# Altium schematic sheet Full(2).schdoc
size 301 x 189 mm
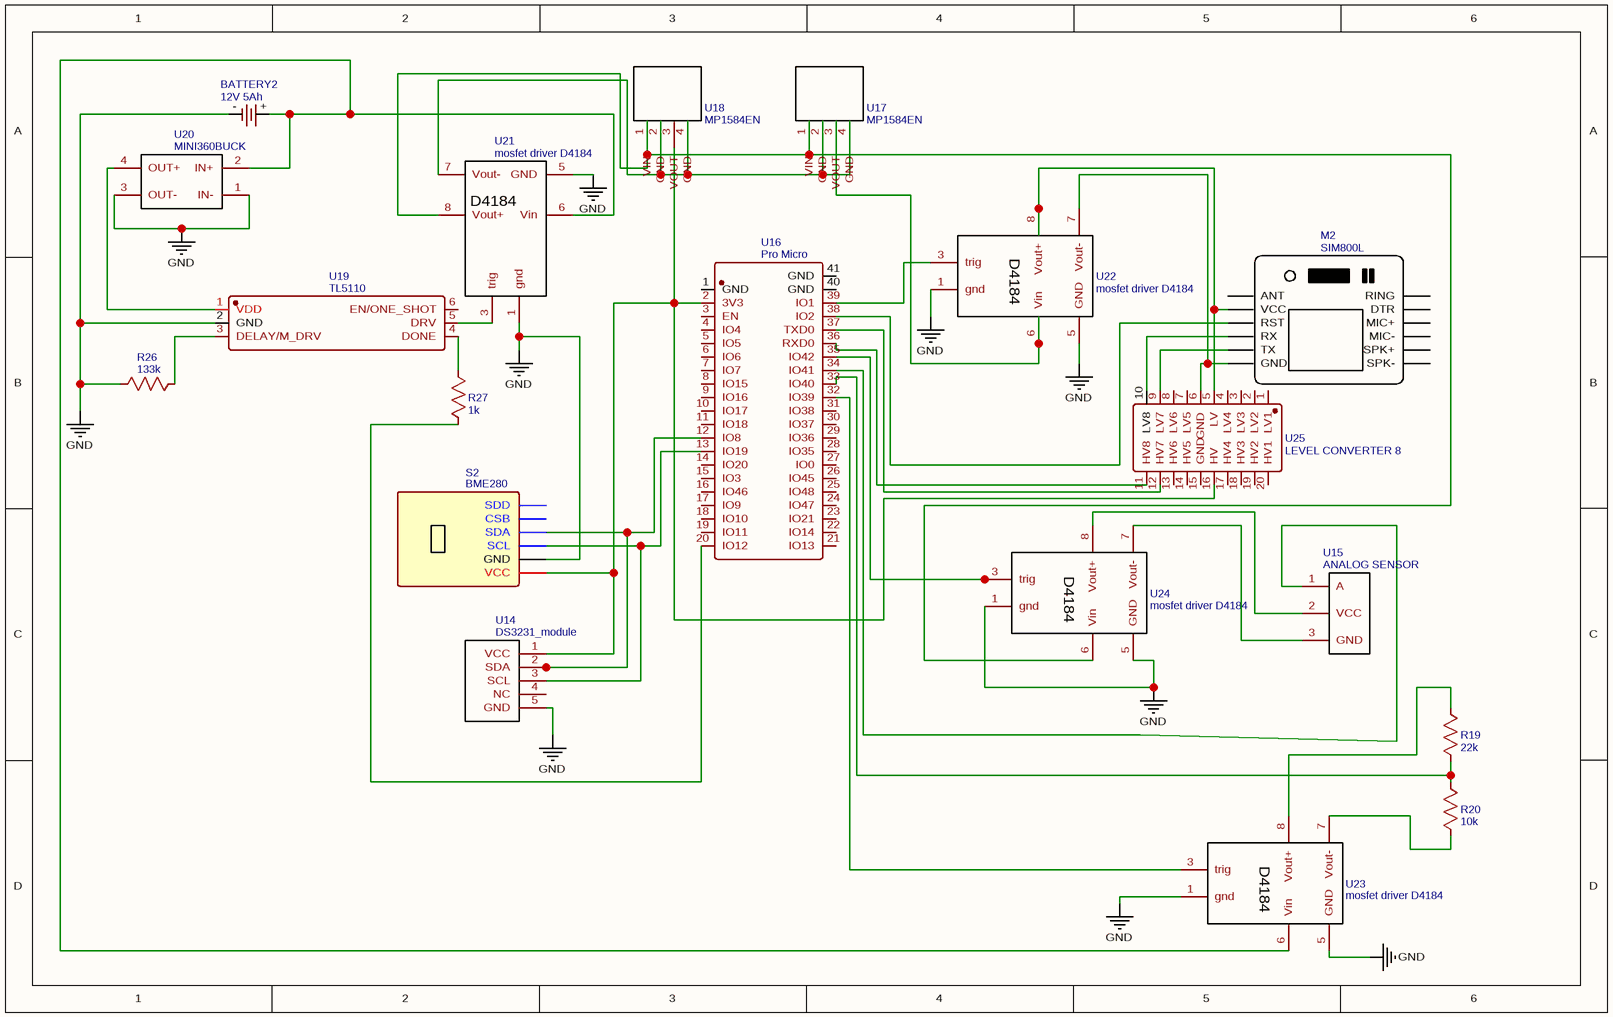
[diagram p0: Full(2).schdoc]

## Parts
BATTERY2  12V 5Ah  [BATTERY-SMD-MY-2032]
M2  SIM800L  [SIM800LMODULE_SIM800LMODULE]
R19  22k  [R0603]
R20  10k  [R0603]
R26  133k  [R0603]
R27  1k  [R0603]
S2  BME280  [BME280]
U14  DS3231_module  [DS3231]
U15  ANALOG SENSOR  [ANALOG SENSOR V1]
U16  Pro Micro  [WIRELM-SMD_ESP32-S3-WROOM-1U]
U17  MP1584EN  [MP1584EN]
U18  MP1584EN  [MP1584EN]
U19  TL5110  [TSOT-23-6_L2.9-W1.6-P0.95-LS2.8-BR]
U20  MINI360BUCK  [MINI360BUCK]
U21  mosfet driver D4184  [D4184]
U22  mosfet driver D4184  [D4184]
U23  mosfet driver D4184  [D4184]
U24  mosfet driver D4184  [D4184]
U25  LEVEL CONVERTER 8  [MPN-TH-20_L28.0-W14.0-P2.54-BL]

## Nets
GND: BATTERY2.-(BAT-) R26.2 S2.2(GND) U14.5(GND) U19.2(GND) U20.1(IN-) U20.3(OUT-) U21.1(gnd) U21.5(GND) U22.1(gnd) U22.5(GND) U23.1(gnd) U23.5(GND) U24.1(gnd) U24.5(GND)
NetBATTERY2_+: BATTERY2.+(BAT+) U20.2(IN+) U21.6(Vin) U23.6(Vin)
NetM2_2: M2.2(VCC) U22.8(Vout+) U25.5(LV)
NetM2_3: M2.3(RST) U16.38(IO2)
NetM2_4: M2.4(RX) U25.10(LV8)
NetM2_5: M2.5(TX) U25.9(LV7)
NetM2_6: M2.6(GND) U22.7(Vout-) U25.6(GND)
NetR19_1: R19.1 U23.8(Vout+)
NetR19_2: R19.2 R20.1 U16.33(IO40)
NetR20_2: R20.2 U23.7(Vout-)
NetR26_1: R26.1 U19.3(DELAY/M_DRV)
NetR27_1: R27.1 U19.4(DONE)
NetR27_2: R27.2 U16.20(IO12)
NetS2_1: S2.1(VCC) U14.1(VCC) U16.2(3V3) U18.3(VOUT) U25.16(HV)
NetS2_3: S2.3(SCL) U14.3(SCL) U16.13(IO19)
NetS2_4: S2.4(SDA) U14.2(SDA) U16.12(IO8)
NetU15_1: U15.1(A) U16.34(IO41)
NetU15_2: U15.2(VCC) U24.8(Vout+)
NetU15_3: U15.3(GND) U24.7(Vout-)
NetU16_32: U16.32(IO39) U23.3(trig)
NetU16_35: U16.35(IO42) U24.3(trig)
NetU16_36: U16.36(RXD0) U25.11(HV8)
NetU16_37: U16.37(TXD0) U25.12(HV7)
NetU16_39: U16.39(IO1) U22.3(trig)
NetU17_1: U17.1(VIN) U18.1(VIN) U21.8(Vout+) U24.6(Vin)
NetU17_2: U17.2(GND) U17.4(GND) U18.2(GND) U18.4(GND) U21.7(Vout-)
NetU17_3: U17.3(VOUT) U22.6(Vin)
NetU19_1: U19.1(VDD) U20.4(OUT+)
NetU19_5: U19.5(DRV) U21.3(trig)

Not connected (* = marked no-connect by the designer): M2 1(ANT) 7(SPK-) 8(SPK+) 9(MIC-) 10(MIC+) 11(DTR) 12(RING); S2 5(CSB) 6(SDD); U14 4(NC); U16 1(GND) 3(EN) 4(IO4) 5(IO5) 6(IO6) 7(IO7) 8(IO15) 9(IO16) 10(IO17) 11(IO18) 14(IO20) 15(IO3) 16(IO46) 17(IO9) 18(IO10) 19(IO11) 21(IO13) 22(IO14) 23(IO21) 24(IO47) 25(IO48) 26(IO45) 27(IO0) 28(IO35) 29(IO36) 30(IO37) 31(IO38) 40(GND) 41(GND); U19 6(EN/ONE_SHOT); U25 1(LV1) 2(LV2) 3(LV3) 4(LV4) 7(LV5) 8(LV6) 13(HV6) 14(HV5) 15(GND) 17(HV4) 18(HV3) 19(HV2) 20(HV1)

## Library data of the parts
BATTERY2 = 12V 5Ah: Manufacturer: MYOUNG(美阳); Manufacturer Part: MY-2032-10; Contributor: lcsc
M2 = SIM800L: Contributor: sharad.rask
R19 = 22k: nameAlias: Value(Ω); Contributor: LCEDA_Lib
R20 = 10k: nameAlias: Value(Ω); Contributor: LCEDA_Lib
R26 = 133k: nameAlias: Value(Ω); Contributor: LCEDA_Lib
R27 = 1k: nameAlias: Value(Ω); Contributor: LCEDA_Lib
U14 = DS3231_module: Contributor: retret
U15 = ANALOG SENSOR: Contributor: utbahR
U16 = Pro Micro: Manufacturer: null; Manufacturer Part: ESP32-S3-WROOM-1U; Contributor: lcsc
U17 U18 = MP1584EN: Contributor: babeinlovexd
U19 = TL5110: Manufacturer: TI(德州仪器); Manufacturer Part: TPL5110DDCR; Contributor: lcsc; nameAlias: Value
U20 = MINI360BUCK: Contributor: Andrey Fedorov; sourceId: FRLFXR8qI
U21-U24 = mosfet driver D4184: Contributor: zahiraauliahusniah
U25 = LEVEL CONVERTER 8: Manufacturer: null; Contributor: LCSC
